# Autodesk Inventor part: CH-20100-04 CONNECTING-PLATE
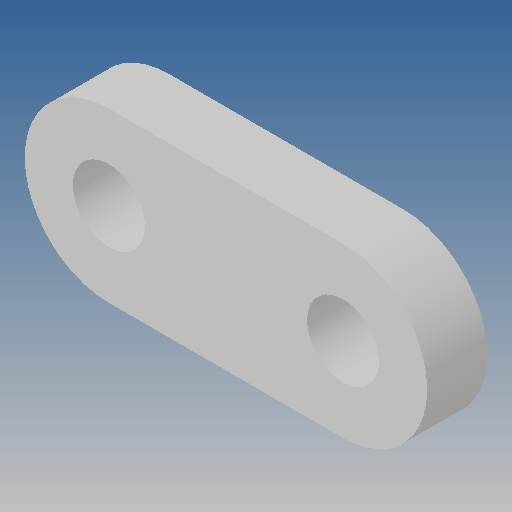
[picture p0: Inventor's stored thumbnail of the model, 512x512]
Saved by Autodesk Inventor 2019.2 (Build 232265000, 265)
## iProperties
Created: 2012-09
Part Number: CH-20100-04 CONNECTING-PLATE
Material: Ogólny
Document SubType Name: Modeling
Designer: CADENGINEERING4
Density: 1 g/cm^3
Appearance: Domyślna
Author: CADENGINEERING4
Revision Number: ÈÎºÎ
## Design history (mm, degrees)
feature "À­Éì1"
node "Bryła1"
